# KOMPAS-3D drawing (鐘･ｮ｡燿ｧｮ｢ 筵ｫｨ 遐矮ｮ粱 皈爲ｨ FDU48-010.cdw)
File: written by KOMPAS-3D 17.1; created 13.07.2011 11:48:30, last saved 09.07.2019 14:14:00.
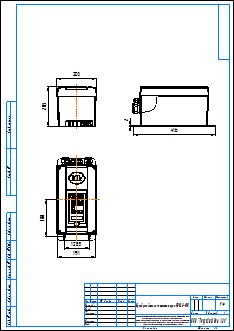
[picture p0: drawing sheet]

Title block, sheet 1: name: Преобразователи частоты серии FDU48-010; scale: 1:4; sheets: 1; sheet format: A3; stored path: \\adlc.lan\data\АДЛ_ПКД\3D-модели\Поставщики\Оборудование Emotron\Преобразователи частоты\Серия FDU 2.0\KOMPAS 2D\Преобразователи частоты серии FDU48-010.cdw

Views: Спереди 1
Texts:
  Рама для чертежей
  Лит-Масса-Масштаб
  Материал-Предприятие
  Масштаб
  Изм.
  Лист
  № докум.
  Подп.
  Дата
  Лит.
  Разраб.
  Пров.
  Т.контр.
  Листов
  Внимание! Данный продукт является объектом авторского права ООО «Торговый Дом АДЛ».
  Запрещается изменение, копирование, распространение
  (в том числе путем копирования на другие сайты и ресурсы в Интернете)
  или любое иное использование информации и объектов без предварительного
  согласия правообладателя (ООО «Торговый Дом АДЛ»).
  Н.контр.
  Утв.
  ООО "Торговый дом АДЛ"
  Изменение
  Номер документа
  Подпись
  Обозначение документа
  Наименование изделия
  Масса изделия по ГОСТ 2.109-73
  Порядковый номер листа
  Общее количество листов в документе
  Характер работы, выполненной лицом, подписавшим документ
  Наименование или индекс предприятия, выпускающего документ
  Инв. № подл.
  Подп. и дата
  Взам. инв. №
  Инв. № дубл.
  Инвентарный номер подлинника по ГОСТ 2.501-68
  Подпись принявшего подлинник в отдел технической документации
  Инвентарный номер подлинника, взамен которого выпущен данный подлинник
  Инвентарный номер дубликата по ГОСТ 2.502-68
  Подпись принявшего дубликат в отдел технической документации
  Справ. №
  Перв. примен.
  Обозначение документа, взамен или на основании которого выпущен данный документ
  Обозначение документа, в котором впервые записан данный документ
  Подпись лица, копировавшего чертеж
  Обозначение формата листа
  !Рама для чертежа
Dimensions and other numbers on the sheet: 203; 128,5; 191; 416; 2; 188; 1:4; 1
